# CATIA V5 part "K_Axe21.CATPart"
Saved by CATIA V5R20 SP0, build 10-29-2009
Part number: Part13
Publications: "Point.1", "Droite.1", "Point.2", "Point.3"
Bounding box of the stored display mesh (mm): x -70 to 95, y -5 to 5, z -4.99 to 4.99
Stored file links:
  G:\Khaled_CFAO_2011\SIL\SIL_GR1\gperrin\Khaled\CAD_CATIA\Khaled\K_Axe21.CATPart
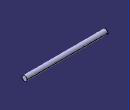
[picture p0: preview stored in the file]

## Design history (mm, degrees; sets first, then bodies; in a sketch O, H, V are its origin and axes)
Body1 (main body)
  Sketch1 on yz-plane, origin (0, 0, 0), H (0, 1, 0), V (0, 0, 1)
    circle A1 centre (0, 0) radius 5
    radius A1 = 5
  Pad1: profile Sketch1, direction (1, 0, 0), length 95, opposite side length 70
  Point1: (0, 0, 0)
  Line1: type Normal, RefPoint Point1, RefSkin end face of Pad1, Start 0, End 300
  Point2: (20, 0, 0)
  Point3: (-20, 0, 0)
  Point4: type Center, Curve edge [face of Pad1 from Sketch1.A1 | end face of Pad1]
  Point5: (-82.5, 0, 0), relative to Point4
